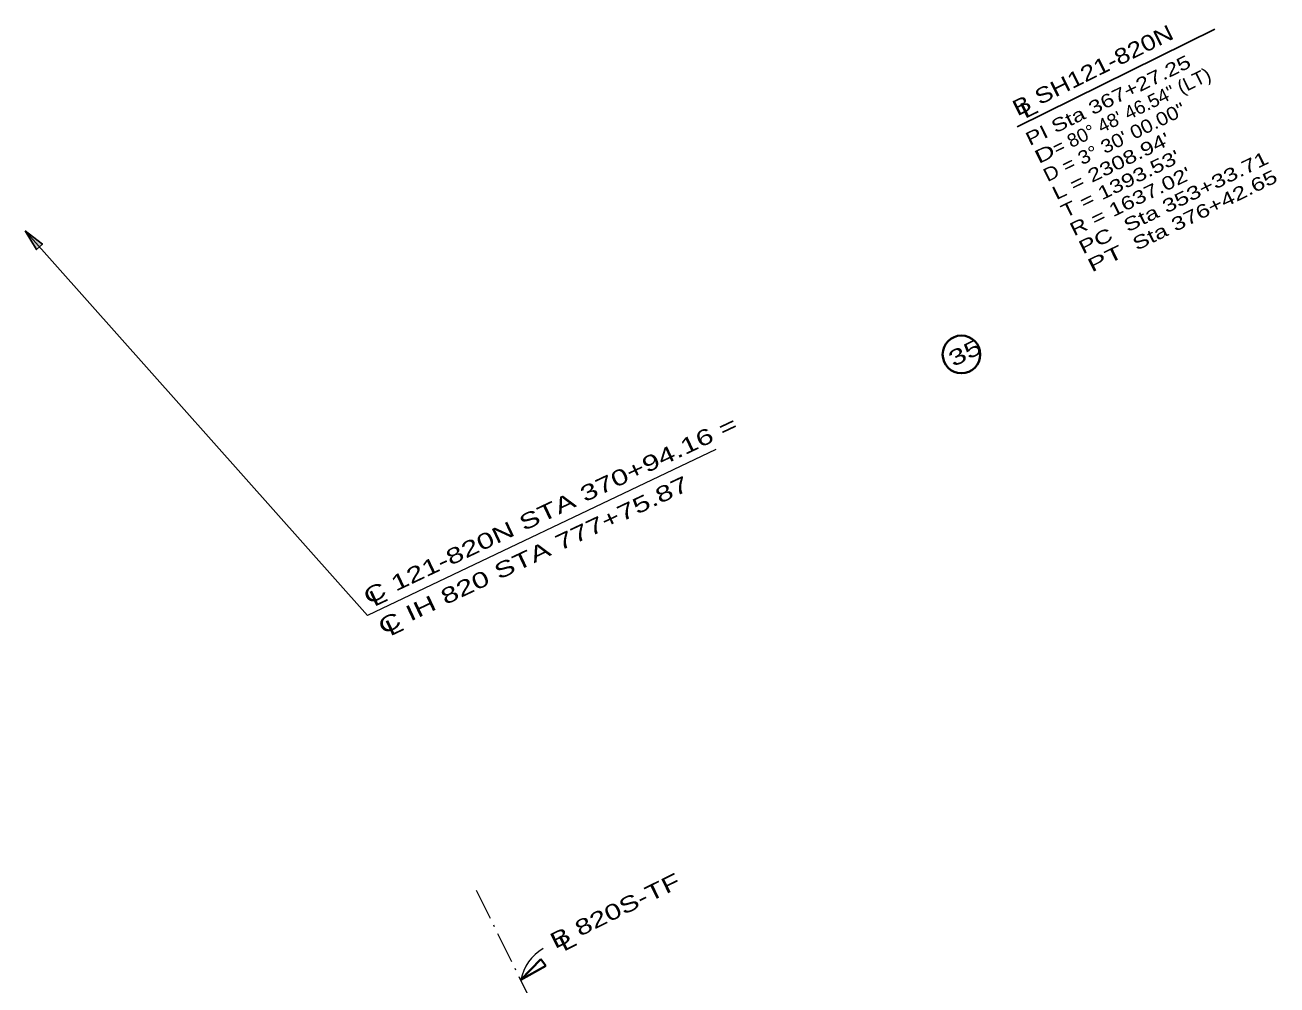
# Model space of a CAD drawing. Extents: x 2356431 to 2371438, y 6972864 to 6982525.
# Drawn here: x 2364499 to 2365619, y 6977927 to 6978785 of the extents above; entities that cross this region are included whole.
import ezdxf
from ezdxf.enums import TextEntityAlignment as Align

# ---------------------------------------------------------------- set-up
doc = ezdxf.new("R2010")
doc.units = 0
doc.header["$LTSCALE"] = 5.6
doc.linetypes.add('DASH_DOUBLE_DOT', pattern=[9.2, 5, -1.2, 0.3, -1.2, 0.3, -1.2])
doc.linetypes.add('DOT_DASHED', pattern=[7.7, 5, -1.2, 0.3, -1.2])
for name, color, linetype, lineweight in [('1', 7, 'Continuous', 25), ('17', 7, 'Continuous', 35), ('28', 7, 'Continuous', 35), ('44', 7, 'Continuous', 13), ('48', 7, 'Continuous', 25), ('53', 7, 'Continuous', 13), ('61', 7, 'Continuous', 13)]:
    doc.layers.add(name, color=color, linetype=linetype, lineweight=lineweight)
doc.layers.add('25', color=7, linetype='Continuous')
doc.layers.add('33', color=7, linetype='Continuous')

msp = doc.modelspace()

# ---------------------------------------------------------------- hatches: boundary and pattern name
at = {"layer": '48'}
msp.add_hatch(color=256, dxfattribs=at).paths.add_polyline_path([(2364499.023, 6978601.193), (2364509.297, 6978584.57), (2364514.615, 6978589.423)])

# ---------------------------------------------------------------- linework, layer by layer
at = {"layer": '1', "lineweight": 13}
msp.add_arc((2364983.569, 6977923.503), 41.969, 120.5749, 168.88863, dxfattribs=at)
at = {"layer": '17'}
msp.add_circle((2365336.415, 6978490.831), 16.828, dxfattribs=at)
at = {"layer": '44', "linetype": 'DOT_DASHED'}
msp.add_line((2364902.524, 6978011.936), (2365035.302, 6977742.903), dxfattribs=at)
at = {"layer": '48', "lineweight": 13}
for p in [(2364499.023, 6978601.193), (2365116.895, 6978405.947)]:
    msp.add_line(p, (2364805.148, 6978257.538), dxfattribs=at)
at = {"layer": '48'}
msp.add_lwpolyline([(2364499.023, 6978601.193), (2364509.297, 6978584.57), (2364514.615, 6978589.423)], close=True, dxfattribs=at)
at = {"layer": '53', "linetype": 'DASH_DOUBLE_DOT', "lineweight": 35}
msp.add_lwpolyline([(2364964.702, 6977944.109), (2364942.385, 6977931.591), (2364960.306, 6977950.159)], close=True, dxfattribs=at)
at = {"layer": '61', "lineweight": 25}
msp.add_line((2365386.192, 6978694.379), (2365563.149, 6978781.714), dxfattribs=at)

# ---------------------------------------------------------------- texts
at = {"layer": '1', "width": 1.4}
for s, p in [('B 820S-TF', (2365029.755, 6977987.228)), ('L', (2364987.092, 6977959.959))]:
    msp.add_text(s, height=14, rotation=26.268, dxfattribs=at).set_placement(p, align=Align.CENTER)
at = {"layer": '17', "width": 1.45}
msp.add_text('35', height=14, rotation=26.268, dxfattribs=at).set_placement((2365342.711, 6978486.132), align=Align.CENTER)
at = {"layer": '25'}
for s, width, p in [('C 121-820N STA 370+94.16 =', 1.45, (2364805.866, 6978267.041)), ('C IH 820 STA 777+75.87', 1.45, (2364819.073, 6978240.275)), ('L', 1.4, (2364811.191, 6978264.969)), ('L', 1.4, (2364825.627, 6978238.64))]:
    msp.add_text(s, height=14, rotation=25.268, dxfattribs=dict(at, width=width)).set_placement(p)
at = {"layer": '28', "width": 1.25}
msp.add_text('B SH121-820N', height=14, rotation=26.377, dxfattribs=at).set_placement((2365457.023, 6978738.662), align=Align.CENTER)
at = {"layer": '33'}
for s, width, p in [('PI Sta 367+27.25', 1.3, (2365397.539, 6978677.065)), ('= 80° 48\' 46.54" (LT)', 1.05, (2365421.619, 6978668.832)), ('D = 3° 30\' 00.00"', 1.15, (2365413.373, 6978644.757)), ("L = 2308.94'", 1.3, (2365421.29, 6978628.603)), ('D', 1.55, (2365405.456, 6978660.911)), ("T = 1393.53'", 1.3, (2365429.208, 6978612.449)), ('Sta 353+33.71', 1.35, (2365485.136, 6978599.825)), ("R = 1637.02'", 1.3, (2365437.125, 6978596.295)), ('Sta 376+42.65', 1.35, (2365493.177, 6978583.419)), ('PC', 1.4, (2365445.042, 6978580.141)), ('PT', 1.6, (2365452.96, 6978563.987))]:
    msp.add_text(s, height=12, rotation=26.11, dxfattribs=dict(at, width=width)).set_placement(p)
at = {"layer": '61', "width": 1.4}
msp.add_text('L', height=14, rotation=26.268, dxfattribs=at).set_placement((2365399.685, 6978704.484), align=Align.CENTER)

doc.saveas('drawing.dxf')
